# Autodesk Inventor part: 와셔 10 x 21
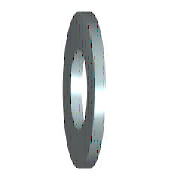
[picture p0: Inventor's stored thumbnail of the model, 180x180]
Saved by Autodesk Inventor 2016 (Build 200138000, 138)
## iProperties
Created: 2012-02
Part Number: 와셔 10 x 21
Material: 강철, 연강
Description: 평면 와셔
Document SubType Name: Modeling
Standard: KS B 1326
Designer: mduedu
Standards Organization: KS
Language: ko-KR
Size Designation: 10x21
Categories: <MemberInstance><Categories><Category DisplayName="조임쇠" InternalName="e4da775c-781d-43d5-af7c-5136215cf5a6" Mnemonic="FSTN"><Category DisplayName="와셔" InternalN
Density: 1 g/cm^3
Appearance: 파란색 - 벽 페인트 - 광택
IsCustomPart: 1
Author: mduedu
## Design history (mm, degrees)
sketch "스케치"
  geometry: C1 r 10.5 at (0, 0); C2 r 5.25 at (0, 0); 1 further point
  constraints: 2 centre point, 2 coincident
  dimensions: "d0" = 10.5 diameter of C2 (= SD1); "d1" = 21 diameter of C1 (= SD2)
extrude "본체" new body sketch "스케치" distance "d2" = 2 (= SD); taper "d3" = 0 deg
workaxis "Work Axis1"
workplane "Work Plane1"
body "Solid1"
other parameters: "SD1" = 10.5 [user parameter; used in 1 equation term], "SD2" = 21 [user parameter; used in 1 equation term], "SD" = 2 [user parameter; used in 1 equation term], "d4" = 0, "d5" = 0, "d6" = 0, "d7" = 0
